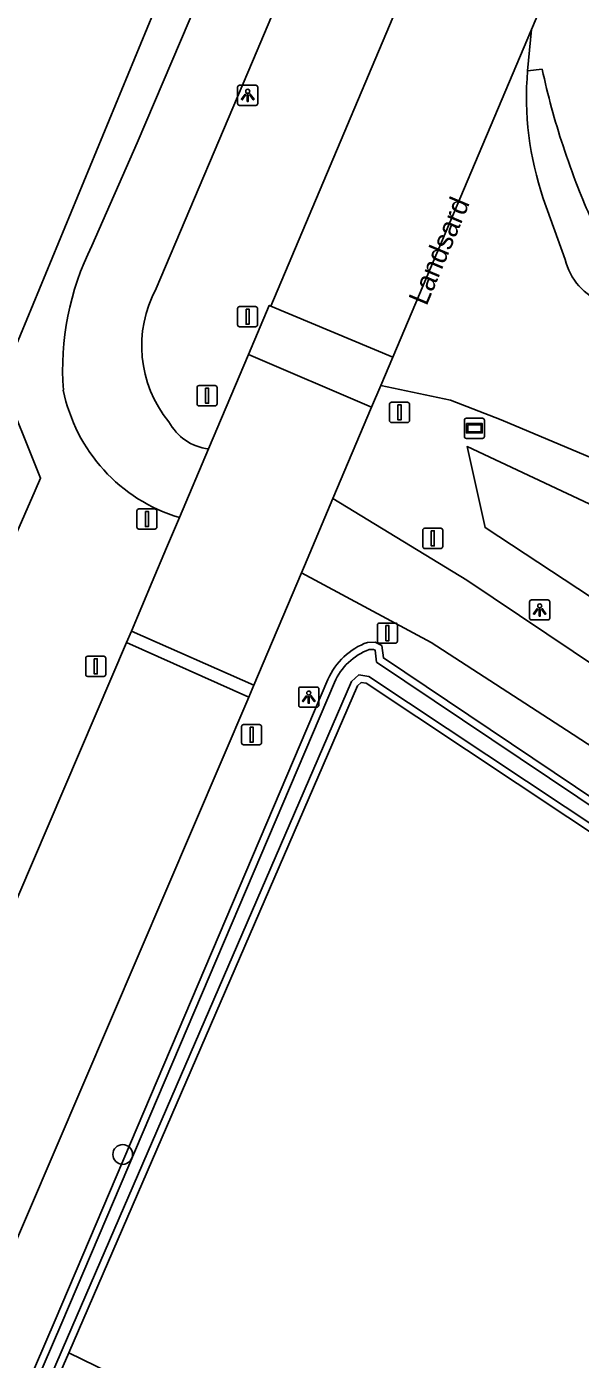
# Model space of a CAD drawing. Extents: x 155209 to 156823, y 385356 to 388482.
# Drawn here: x 155998.6 to 156026, y 386144.1 to 386210 of the extents above; entities that cross this region are included whole.
import ezdxf

# ---------------------------------------------------------------- set-up
doc = ezdxf.new("R2010")
doc.units = 0
for name, color, linetype in [('IMGEO_Berm_gesloten', 7, 'Continuous'), ('IMGEO_Berm_groen', 7, 'Continuous'), ('IMGEO_Boom', 7, 'Continuous'), ('IMGEO_Erf', 7, 'Continuous'), ('IMGEO_Fietspad_gesloten', 7, 'Continuous'), ('IMGEO_Hek', 7, 'Continuous'), ('IMGEO_Lichtpunt', 7, 'Continuous'), ('IMGEO_Naaldbos', 7, 'Continuous'), ('IMGEO_Openbare_ruimte_label', 7, 'Continuous'), ('IMGEO_Rijbaan_lokaal_gesloten', 7, 'Continuous'), ('IMGEO_Rijbaan_lokaal_open', 7, 'Continuous'), ('IMGEO_Straatnaambord', 7, 'Continuous'), ('IMGEO_Verkeersbordpaal', 7, 'Continuous'), ('IMGEO_Waterloop', 7, 'Continuous')]:
    doc.layers.add(name, color=color, linetype=linetype)

msp = doc.modelspace()

# ---------------------------------------------------------------- linework, layer by layer
at = {"layer": 'IMGEO_Berm_gesloten'}
msp.add_lwpolyline([(156023.385, 386207.816), (156024.112, 386207.892)], dxfattribs=at)
for centre, radius, start, end in [((156058.078, 386215.056), 34.714, 191.91019, 198.39795), ((156061.966, 386216.168), 38.754, 198.14437, 201.36833), ((156062.26, 386216.387), 39.108, 201.50988, 204.08142)]:
    msp.add_arc(centre, radius, start, end, dxfattribs=at)
at = {"layer": 'IMGEO_Berm_groen'}
for points in [[(155916.981, 385994.929), (155959.302, 386096.168), (155999.017, 386187.05), (155999.279, 386187.649), (155997.339, 386192.467), (156017.719, 386241.801), (156020.329, 386248.119)], [(156033.061, 386177.459), (156021.284, 386185.214), (156020.389, 386189.219), (156031.664, 386183.929), (156073.255, 386164.351), (156077.439, 386161.836)], [(156049.296, 386156.966), (156028.926, 386170.26), (156016.248, 386178.762), (156016.169, 386179.377), (156015.839, 386179.549), (156015.467, 386179.533)], [(156013.501, 386177.695), (156000, 386146.004), (155952.015, 386034.682)]]:
    msp.add_lwpolyline(points, dxfattribs=at)
msp.add_arc((156016.601, 386176.349), 3.38, 109.60897, 156.53662, dxfattribs=at)
at = {"layer": 'IMGEO_Boom'}
msp.add_circle((156003.346, 386154.198), 0.489, dxfattribs=at)
at = {"layer": 'IMGEO_Erf'}
msp.add_lwpolyline([(156049.296, 386156.966), (156048.886, 386156.32), (156048.518, 386155.741), (156032.854, 386165.927), (156015.392, 386177.509), (156015.147, 386177.545), (156014.962, 386177.381), (156000.676, 386144.39)], dxfattribs=at)
at = {"layer": 'IMGEO_Fietspad_gesloten'}
for points in [[(156142.588, 386521.008), (156114.612, 386455.401), (156091.234, 386400.622), (156069.84, 386350.227), (156058.063, 386322.415), (156046.408, 386294.89), (156023.008, 386239.564), (156010.003, 386208.816), (156004.996, 386197.039)], [(156054.538, 386323.386), (156042.977, 386296.079), (156023.427, 386249.93), (156022.289, 386247.244), (156019.639, 386240.989), (156006.628, 386210.275), (156004.066, 386204.243), (156001.816, 386199.144)]]:
    msp.add_lwpolyline(points, dxfattribs=at)
for centre, radius, start, end in [((156014.042, 386193.021), 13.673, 153.3985, 184.23817), ((156010.253, 386194.215), 5.968, 151.75594, 219.16082), ((156008.54, 386193.651), 8.298, 191.40063, 253.2588), ((156007.906, 386191.675), 2.59, 208.32341, 263.01421)]:
    msp.add_arc(centre, radius, start, end, dxfattribs=at)
at = {"layer": 'IMGEO_Hek'}
msp.add_lwpolyline([(155979.683, 386081.47), (155987.477, 386099.578), (156000, 386126.796), (156006.735, 386141.433), (156000.676, 386144.39)], dxfattribs=at)
at = {"layer": 'IMGEO_Lichtpunt'}
for p, q in [((156009.033, 386206.998), (156009.033, 386206.191)), ((156009.033, 386206.998), (156009.033, 386206.191)), ((156009.935, 386207.093), (156009.127, 386207.093)), ((156009.935, 386207.093), (156009.127, 386207.093)), ((156010.029, 386206.191), (156010.029, 386206.998)), ((156010.029, 386206.191), (156010.029, 386206.998)), ((156009.127, 386206.097), (156009.935, 386206.097)), ((156009.127, 386206.097), (156009.935, 386206.097)), ((156023.485, 386181.541), (156023.485, 386180.734)), ((156023.485, 386181.541), (156023.485, 386180.734)), ((156024.387, 386181.636), (156023.579, 386181.636)), ((156024.387, 386181.636), (156023.579, 386181.636)), ((156024.481, 386180.734), (156024.481, 386181.541)), ((156024.481, 386180.734), (156024.481, 386181.541)), ((156023.579, 386180.64), (156024.387, 386180.64)), ((156023.579, 386180.64), (156024.387, 386180.64)), ((156012.055, 386177.229), (156012.055, 386176.422)), ((156012.055, 386177.229), (156012.055, 386176.422)), ((156012.957, 386177.324), (156012.149, 386177.324)), ((156012.957, 386177.324), (156012.149, 386177.324)), ((156013.051, 386176.422), (156013.051, 386177.229)), ((156013.051, 386176.422), (156013.051, 386177.229)), ((156012.149, 386176.328), (156012.957, 386176.328)), ((156012.149, 386176.328), (156012.957, 386176.328))]:
    msp.add_line(p, q, dxfattribs=at)
for points in [[(156009.407, 386206.662), (156009.446, 386206.634), (156009.258, 386206.372), (156009.22, 386206.399), (156009.407, 386206.662)], [(156009.509, 386206.614), (156009.556, 386206.614), (156009.556, 386206.292), (156009.509, 386206.292), (156009.509, 386206.614)], [(156009.619, 386206.634), (156009.657, 386206.661), (156009.844, 386206.399), (156009.805, 386206.371), (156009.619, 386206.634)], [(156023.859, 386181.205), (156023.898, 386181.177), (156023.71, 386180.915), (156023.672, 386180.942), (156023.859, 386181.205)], [(156023.961, 386181.157), (156024.008, 386181.157), (156024.008, 386180.835), (156023.961, 386180.835), (156023.961, 386181.157)], [(156024.071, 386181.177), (156024.109, 386181.204), (156024.296, 386180.942), (156024.257, 386180.914), (156024.071, 386181.177)], [(156012.429, 386176.893), (156012.468, 386176.865), (156012.28, 386176.603), (156012.242, 386176.63), (156012.429, 386176.893)], [(156012.531, 386176.845), (156012.578, 386176.845), (156012.578, 386176.523), (156012.531, 386176.523), (156012.531, 386176.845)], [(156012.641, 386176.865), (156012.679, 386176.892), (156012.866, 386176.63), (156012.827, 386176.602), (156012.641, 386176.865)]]:
    msp.add_lwpolyline(points, dxfattribs=at)
for centre in [(156009.532, 386206.796), (156023.984, 386181.339), (156012.554, 386177.027)]:
    msp.add_circle(centre, 0.0994, dxfattribs=at)
for centre, start, end in [((156009.127, 386206.998), 90, 180), ((156009.127, 386206.998), 90, 180), ((156009.935, 386206.998), 0, 90), ((156009.935, 386206.998), 0, 90), ((156009.127, 386206.191), 180, 270), ((156009.127, 386206.191), 180, 270), ((156009.935, 386206.191), 270, 0), ((156009.935, 386206.191), 270, 360), ((156023.579, 386181.541), 90, 180), ((156023.579, 386181.541), 90, 180), ((156024.387, 386181.541), 0, 90), ((156024.387, 386181.541), 0, 90), ((156023.579, 386180.734), 180, 270), ((156023.579, 386180.734), 180, 270), ((156024.387, 386180.734), 270, 0), ((156024.387, 386180.734), 270, 360), ((156012.149, 386177.229), 90, 180), ((156012.149, 386177.229), 90, 180), ((156012.957, 386177.229), 0, 90), ((156012.957, 386177.229), 0, 90), ((156012.149, 386176.422), 180, 270), ((156012.149, 386176.422), 180, 270), ((156012.957, 386176.422), 270, 0), ((156012.957, 386176.422), 270, 360)]:
    msp.add_arc(centre, 0.0946, start, end, dxfattribs=at)
at = {"layer": 'IMGEO_Naaldbos'}
for points in [[(156000.676, 386144.39), (156000, 386142.83), (155975.488, 386085.88), (155975.714, 386085.504)], [(156000.676, 386144.39), (156006.735, 386141.433), (156000, 386126.796), (155987.477, 386099.578), (155979.683, 386081.47)]]:
    msp.add_lwpolyline(points, dxfattribs=at)
at = {"layer": 'IMGEO_Rijbaan_lokaal_gesloten'}
for points in [[(156010.669, 386196.174), (156028.113, 386237.404), (156051.194, 386291.958), (156074.965, 386348.058), (156088.146, 386379.283), (156100.534, 386408.284), (156128.809, 386474.423), (156158.862, 386544.699), (156160.628, 386548.864)], [(156164.881, 386542.108), (156134.859, 386471.858), (156106.547, 386405.649), (156094.197, 386376.746), (156080.926, 386345.397), (156057.345, 386289.662), (156034.159, 386234.847), (156023.573, 386209.847)], [(156016.712, 386193.643), (156023.573, 386209.847)], [(156023.573, 386209.847), (156023.385, 386207.816)], [(156025.241, 386198.475), (156024.163, 386201.492)], [(156067.725, 386171.243), (156063.134, 386173.252), (156022.073, 386190.539), (156019.563, 386191.511), (156016.121, 386192.247)], [(156070.659, 386149.306), (156068.33, 386150.873), (156056.89, 386158.505), (156026.946, 386178.211), (156020.382, 386182.613), (156013.752, 386186.657)], [(156012.192, 386182.976), (156018.608, 386179.531), (156025.311, 386175.189), (156049.349, 386159.56)], [(156003.535, 386179.533), (155989.702, 386147.215), (155959.53, 386076.883), (155927.744, 386002.822)], [(155949.137, 386035.922), (155965.644, 386074.344), (155984.914, 386119.233), (156009.585, 386176.823)]]:
    msp.add_lwpolyline(points, dxfattribs=at)
for centre, radius, start, end in [((156038.826, 386206.506), 15.496, 175.14951, 198.87745), ((156028.205, 386199.202), 3.052, 193.77559, 249.67778)]:
    msp.add_arc(centre, radius, start, end, dxfattribs=at)
at = {"layer": 'IMGEO_Rijbaan_lokaal_open'}
for points in [[(156009.569, 386193.772), (156010.599, 386196.203), (156010.669, 386196.174)], [(156010.669, 386196.174), (156016.712, 386193.643)], [(156007.591, 386189.104), (156009.569, 386193.772)], [(156015.665, 386191.171), (156009.569, 386193.772)], [(156016.712, 386193.643), (156016.121, 386192.247)], [(156016.121, 386192.247), (156015.665, 386191.171)], [(156013.752, 386186.657), (156015.665, 386191.171)], [(156006.15, 386185.705), (156007.591, 386189.104)], [(156013.752, 386186.657), (156012.339, 386183.322), (156012.192, 386182.976)], [(156006.15, 386185.705), (156005.515, 386184.205), (156004.801, 386182.521), (156003.773, 386180.094)], [(156009.838, 386177.421), (156012.192, 386182.976)], [(156003.773, 386180.094), (156003.535, 386179.533)], [(156009.585, 386176.823), (156003.535, 386179.533)], [(156009.838, 386177.421), (156003.773, 386180.094)], [(156009.585, 386176.823), (156009.838, 386177.421)]]:
    msp.add_lwpolyline(points, dxfattribs=at)
at = {"layer": 'IMGEO_Straatnaambord'}
for p, q in [((156020.256, 386189.723), (156020.256, 386190.523)), ((156020.256, 386190.523), (156020.256, 386189.723)), ((156020.356, 386190.623), (156021.146, 386190.623)), ((156021.146, 386190.623), (156020.356, 386190.623)), ((156021.246, 386190.523), (156021.246, 386189.723)), ((156021.246, 386189.723), (156021.246, 386190.523)), ((156021.146, 386189.623), (156020.356, 386189.623)), ((156020.356, 386189.623), (156021.146, 386189.623))]:
    msp.add_line(p, q, dxfattribs=at)
for points in [[(156020.357, 386190.355), (156021.145, 386190.355), (156021.145, 386189.891), (156020.357, 386189.891), (156020.357, 386190.355)], [(156020.422, 386190.29), (156020.422, 386189.956), (156021.08, 386189.956), (156021.08, 386190.29), (156020.422, 386190.29)]]:
    msp.add_lwpolyline(points, dxfattribs=at)
for centre, start, end in [((156020.356, 386190.523), 90, 180), ((156020.356, 386190.523), 90, 180), ((156021.146, 386190.523), 0, 90), ((156021.146, 386190.523), 360, 90), ((156020.356, 386189.723), 180, 270), ((156020.356, 386189.723), 180, 270), ((156021.146, 386189.723), 270, 0), ((156021.146, 386189.723), 270, 0)]:
    msp.add_arc(centre, 0.1, start, end, dxfattribs=at)
at = {"layer": 'IMGEO_Verkeersbordpaal'}
for p, q in [((156009.029, 386195.244), (156009.029, 386196.044)), ((156009.029, 386196.044), (156009.029, 386195.244)), ((156009.129, 386196.144), (156009.919, 386196.144)), ((156009.919, 386196.144), (156009.129, 386196.144)), ((156010.019, 386196.044), (156010.019, 386195.244)), ((156010.019, 386195.244), (156010.019, 386196.044)), ((156009.919, 386195.144), (156009.129, 386195.144)), ((156009.129, 386195.144), (156009.919, 386195.144)), ((156007.025, 386191.334), (156007.025, 386192.134)), ((156007.025, 386192.134), (156007.025, 386191.334)), ((156007.125, 386192.234), (156007.915, 386192.234)), ((156007.915, 386192.234), (156007.125, 386192.234)), ((156008.015, 386192.134), (156008.015, 386191.334)), ((156008.015, 386191.334), (156008.015, 386192.134)), ((156016.65, 386191.41), (156017.44, 386191.41)), ((156017.44, 386191.41), (156016.65, 386191.41)), ((156007.915, 386191.234), (156007.125, 386191.234)), ((156007.125, 386191.234), (156007.915, 386191.234)), ((156016.55, 386190.51), (156016.55, 386191.31)), ((156016.55, 386191.31), (156016.55, 386190.51)), ((156017.54, 386191.31), (156017.54, 386190.51)), ((156017.54, 386190.51), (156017.54, 386191.31)), ((156017.44, 386190.41), (156016.65, 386190.41)), ((156016.65, 386190.41), (156017.44, 386190.41)), ((156004.147, 386186.134), (156004.937, 386186.134)), ((156004.937, 386186.134), (156004.147, 386186.134)), ((156004.047, 386185.234), (156004.047, 386186.034)), ((156004.047, 386186.034), (156004.047, 386185.234)), ((156005.037, 386186.034), (156005.037, 386185.234)), ((156005.037, 386185.234), (156005.037, 386186.034)), ((156004.937, 386185.134), (156004.147, 386185.134)), ((156004.147, 386185.134), (156004.937, 386185.134)), ((156018.196, 386184.277), (156018.196, 386185.077)), ((156018.196, 386185.077), (156018.196, 386184.277)), ((156018.296, 386185.177), (156019.086, 386185.177)), ((156019.086, 386185.177), (156018.296, 386185.177)), ((156019.186, 386185.077), (156019.186, 386184.277)), ((156019.186, 386184.277), (156019.186, 386185.077)), ((156019.086, 386184.177), (156018.296, 386184.177)), ((156018.296, 386184.177), (156019.086, 386184.177)), ((156015.953, 386179.59), (156015.953, 386180.39)), ((156015.953, 386180.39), (156015.953, 386179.59)), ((156016.053, 386180.49), (156016.843, 386180.49)), ((156016.843, 386180.49), (156016.053, 386180.49)), ((156016.943, 386180.39), (156016.943, 386179.59)), ((156016.943, 386179.59), (156016.943, 386180.39)), ((156016.843, 386179.49), (156016.053, 386179.49)), ((156016.053, 386179.49), (156016.843, 386179.49)), ((156001.614, 386178.849), (156002.404, 386178.849)), ((156002.404, 386178.849), (156001.614, 386178.849)), ((156001.514, 386177.949), (156001.514, 386178.749)), ((156001.514, 386178.749), (156001.514, 386177.949)), ((156002.504, 386178.749), (156002.504, 386177.949)), ((156002.504, 386177.949), (156002.504, 386178.749)), ((156002.404, 386177.849), (156001.614, 386177.849)), ((156001.614, 386177.849), (156002.404, 386177.849)), ((156009.227, 386174.564), (156009.227, 386175.364)), ((156009.227, 386175.364), (156009.227, 386174.564)), ((156009.327, 386175.464), (156010.117, 386175.464)), ((156010.117, 386175.464), (156009.327, 386175.464)), ((156010.217, 386175.364), (156010.217, 386174.564)), ((156010.217, 386174.564), (156010.217, 386175.364)), ((156010.117, 386174.464), (156009.327, 386174.464)), ((156009.327, 386174.464), (156010.117, 386174.464))]:
    msp.add_line(p, q, dxfattribs=at)
for points in [[(156009.449, 386196.019), (156009.599, 386196.019), (156009.599, 386195.269), (156009.449, 386195.269), (156009.449, 386196.019)], [(156007.445, 386192.109), (156007.595, 386192.109), (156007.595, 386191.359), (156007.445, 386191.359), (156007.445, 386192.109)], [(156016.97, 386191.285), (156017.12, 386191.285), (156017.12, 386190.535), (156016.97, 386190.535), (156016.97, 386191.285)], [(156004.467, 386186.009), (156004.617, 386186.009), (156004.617, 386185.259), (156004.467, 386185.259), (156004.467, 386186.009)], [(156018.616, 386185.052), (156018.766, 386185.052), (156018.766, 386184.302), (156018.616, 386184.302), (156018.616, 386185.052)], [(156016.373, 386180.365), (156016.523, 386180.365), (156016.523, 386179.615), (156016.373, 386179.615), (156016.373, 386180.365)], [(156001.934, 386178.724), (156002.084, 386178.724), (156002.084, 386177.974), (156001.934, 386177.974), (156001.934, 386178.724)], [(156009.647, 386175.339), (156009.797, 386175.339), (156009.797, 386174.589), (156009.647, 386174.589), (156009.647, 386175.339)]]:
    msp.add_lwpolyline(points, dxfattribs=at)
for centre, start, end in [((156009.129, 386196.044), 90, 180), ((156009.129, 386196.044), 90, 180), ((156009.919, 386196.044), 0, 90), ((156009.919, 386196.044), 360, 90), ((156009.129, 386195.244), 180, 270), ((156009.129, 386195.244), 180, 270), ((156009.919, 386195.244), 270, 0), ((156009.919, 386195.244), 270, 0), ((156007.125, 386192.134), 90, 180), ((156007.125, 386192.134), 90, 180), ((156007.915, 386192.134), 0, 90), ((156007.915, 386192.134), 360, 90), ((156016.65, 386191.31), 90, 180), ((156016.65, 386191.31), 90, 180), ((156017.44, 386191.31), 0, 90), ((156017.44, 386191.31), 360, 90), ((156007.125, 386191.334), 180, 270), ((156007.125, 386191.334), 180, 270), ((156007.915, 386191.334), 270, 0), ((156007.915, 386191.334), 270, 0), ((156016.65, 386190.51), 180, 270), ((156016.65, 386190.51), 180, 270), ((156017.44, 386190.51), 270, 0), ((156017.44, 386190.51), 270, 0), ((156004.147, 386186.034), 90, 180), ((156004.147, 386186.034), 90, 180), ((156004.937, 386186.034), 0, 90), ((156004.937, 386186.034), 360, 90), ((156004.147, 386185.234), 180, 270), ((156004.147, 386185.234), 180, 270), ((156004.937, 386185.234), 270, 0), ((156004.937, 386185.234), 270, 0), ((156018.296, 386185.077), 90, 180), ((156018.296, 386185.077), 90, 180), ((156019.086, 386185.077), 0, 90), ((156019.086, 386185.077), 360, 90), ((156018.296, 386184.277), 180, 270), ((156018.296, 386184.277), 180, 270), ((156019.086, 386184.277), 270, 0), ((156019.086, 386184.277), 270, 0), ((156016.053, 386180.39), 90, 180), ((156016.053, 386180.39), 90, 180), ((156016.843, 386180.39), 0, 90), ((156016.843, 386180.39), 360, 90), ((156016.053, 386179.59), 180, 270), ((156016.053, 386179.59), 180, 270), ((156016.843, 386179.59), 270, 0), ((156016.843, 386179.59), 270, 0), ((156001.614, 386178.749), 90, 180), ((156001.614, 386178.749), 90, 180), ((156002.404, 386178.749), 0, 90), ((156002.404, 386178.749), 360, 90), ((156001.614, 386177.949), 180, 270), ((156001.614, 386177.949), 180, 270), ((156002.404, 386177.949), 270, 0), ((156002.404, 386177.949), 270, 0), ((156009.327, 386175.364), 90, 180), ((156009.327, 386175.364), 90, 180), ((156010.117, 386175.364), 0, 90), ((156010.117, 386175.364), 360, 90), ((156009.327, 386174.564), 180, 270), ((156009.327, 386174.564), 180, 270), ((156010.117, 386174.564), 270, 0), ((156010.117, 386174.564), 270, 0)]:
    msp.add_arc(centre, 0.1, start, end, dxfattribs=at)
at = {"layer": 'IMGEO_Waterloop'}
for points in [[(156015.538, 386179.179), (156015.759, 386179.188), (156015.839, 386179.147), (156015.914, 386178.556), (156028.729, 386169.962), (156048.806, 386156.86), (156048.585, 386156.512), (156048.41, 386156.237), (156033.05, 386166.225), (156015.523, 386177.851), (156015.034, 386177.922), (156014.666, 386177.596), (156000.348, 386144.532), (155999.672, 386142.972), (155975.088, 386085.853), (155975.313, 386085.477), (155942.794, 386010.259)], [(155942.794, 386010.259), (155942.162, 386010.92), (156000.328, 386145.863), (156013.829, 386177.554)]]:
    msp.add_lwpolyline(points, dxfattribs=at)
msp.add_arc((156016.617, 386176.333), 3.044, 110.76625, 156.34723, dxfattribs=at)

# ---------------------------------------------------------------- texts
at = {"layer": 'IMGEO_Openbare_ruimte_label'}
msp.add_text('Landsard', height=1, rotation=67.23027, dxfattribs=at).set_placement((156018.383, 386196.142))

doc.saveas('drawing.dxf')
